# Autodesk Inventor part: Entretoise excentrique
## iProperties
Author: Flavien MARTY
Shininess: 27.0
PropertySet Name: _Private Model Information
Created: 2001-10
Part Number: Entretoise excentrique
Material: Par défaut
Document SubType Name: Modélisation
Designer: Flavien MARTY
Control State: 0
Master: False
Checked Out: False
PropertySet Name: Design Tracking Control
Density: 0.0
Volumn: 0.0
Area: 0.0
PropertySet Name: Model Information
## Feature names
1. Base1
